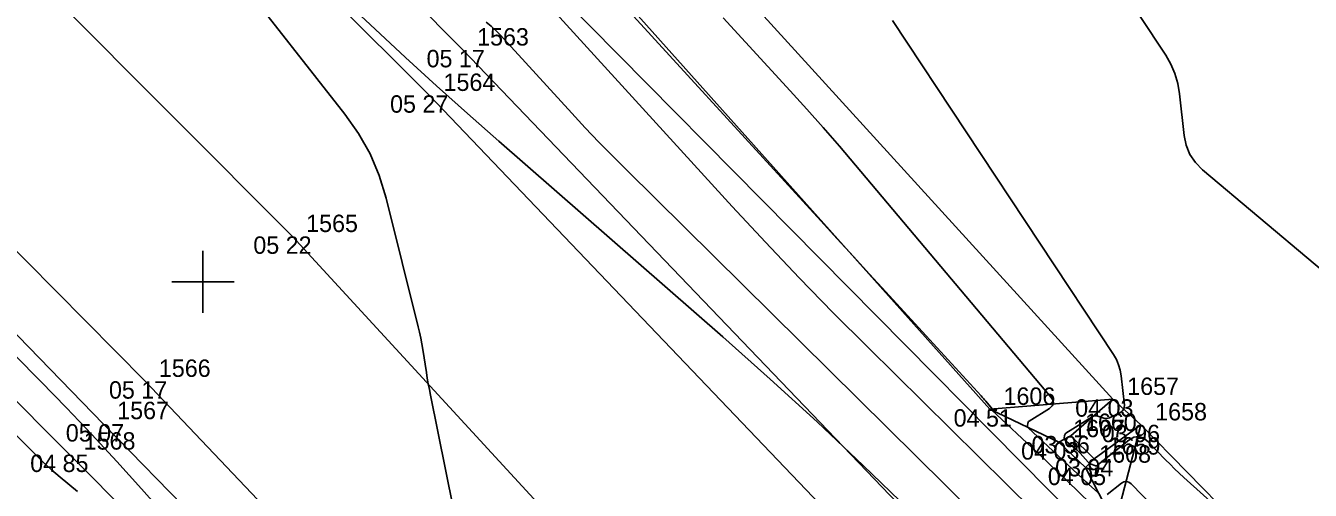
# Model space of a CAD drawing. Extents: x -711234 to -710007, y -1026313 to -1025448.
# Drawn here: x -710352.85 to -710332.18, y -1025703.35 to -1025695.88 of the extents above; entities that cross this region are included whole.
import ezdxf

# ---------------------------------------------------------------- set-up
doc = ezdxf.new("R2010")
doc.units = 0
for name, color, linetype in [('Ex_Major Contours', 7, 'Continuous'), ('Ex_Minor Contours', 7, 'Continuous'), ('Z_body', 7, 'Continuous'), ('Z_body_cisla', 7, 'Continuous'), ('Z_body_vysky_redukovane', 7, 'Continuous'), ('Z_hektometricka_sit', 7, 'Continuous'), ('Z_hrany_paty', 7, 'Continuous'), ('Z_katastr_hranice', 7, 'Continuous'), ('Z_komunikace', 7, 'Continuous'), ('Z_komunikace_osa', 7, 'Continuous'), ('Z_pole_rozhranni', 7, 'Continuous')]:
    doc.layers.add(name, color=color, linetype=linetype)

# ---------------------------------------------------------------- blocks, each defined once
blk = doc.blocks.new('POINT_DISPLAY')
blk.add_line((0, 0), (0, 0))

msp = doc.modelspace()

# ---------------------------------------------------------------- linework, layer by layer
at = {"layer": 'Ex_Major Contours'}
for points in [[(-710361.606, -1025693.861), (-710352.57, -1025702.9), (-710352.505, -1025702.963), (-710352.438, -1025703.025), (-710352.37, -1025703.086), (-710352.3, -1025703.145), (-710352.018, -1025703.376)], [(-710345.446, -1025695.826), (-710345.364, -1025695.889), (-710345.286, -1025695.959), (-710345.212, -1025696.034), (-710344.065, -1025697.289), (-710343.849, -1025697.522), (-710343.63, -1025697.753), (-710343.408, -1025697.981), (-710343.182, -1025698.206), (-710337.591, -1025703.725)], [(-710338.909, -1025695.795), (-710335.352, -1025701.172), (-710335.305, -1025701.252), (-710335.27, -1025701.335), (-710335.244, -1025701.422), (-710335.229, -1025701.512), (-710335.176, -1025701.985), (-710335.177, -1025702.022), (-710335.188, -1025702.054), (-710335.209, -1025702.081), (-710335.24, -1025702.102), (-710335.415, -1025702.188), (-710335.437, -1025702.196), (-710335.461, -1025702.2), (-710335.484, -1025702.199), (-710335.508, -1025702.193), (-710335.604, -1025702.16), (-710335.627, -1025702.154), (-710335.65, -1025702.154), (-710335.673, -1025702.159), (-710335.694, -1025702.17), (-710336.116, -1025702.437), (-710336.124, -1025702.443), (-710336.131, -1025702.451), (-710336.135, -1025702.46), (-710336.138, -1025702.471), (-710336.145, -1025702.515), (-710336.146, -1025702.526), (-710336.143, -1025702.535), (-710336.138, -1025702.544), (-710336.131, -1025702.551), (-710335.987, -1025702.664), (-710335.961, -1025702.686), (-710335.935, -1025702.709), (-710335.911, -1025702.733), (-710335.888, -1025702.758), (-710335.756, -1025702.904), (-710335.746, -1025702.915), (-710335.734, -1025702.923), (-710335.722, -1025702.93), (-710335.708, -1025702.936), (-710335.652, -1025702.955), (-710335.638, -1025702.958), (-710335.625, -1025702.958), (-710335.613, -1025702.954), (-710335.601, -1025702.946), (-710335.102, -1025702.549), (-710335.023, -1025702.502), (-710334.946, -1025702.489), (-710334.871, -1025702.512), (-710334.799, -1025702.568), (-710334.513, -1025702.862), (-710334.441, -1025702.935), (-710334.368, -1025703.007), (-710334.294, -1025703.078), (-710334.218, -1025703.147), (-710333.639, -1025703.671)], [(-710347.01, -1025707.804), (-710350.989, -1025703.329), (-710351.385, -1025702.89), (-710351.787, -1025702.457), (-710352.194, -1025702.029), (-710352.608, -1025701.606), (-710354.273, -1025699.928)]]:
    msp.add_lwpolyline(points, dxfattribs=at)
at = {"layer": 'Ex_Minor Contours'}
for points in [[(-710330.296, -1025701.243), (-710333.918, -1025698.198), (-710334.033, -1025698.082), (-710334.121, -1025697.951), (-710334.181, -1025697.805), (-710334.213, -1025697.645), (-710334.288, -1025696.974), (-710334.316, -1025696.81), (-710334.362, -1025696.652), (-710334.428, -1025696.501), (-710334.511, -1025696.357), (-710337.061, -1025692.503)], [(-710349.875, -1025693.472), (-710347.232, -1025695.939), (-710346.74, -1025696.394), (-710346.245, -1025696.846), (-710345.745, -1025697.293), (-710345.242, -1025697.736), (-710341.638, -1025700.886), (-710340.874, -1025701.564), (-710340.121, -1025702.253), (-710339.378, -1025702.953), (-710338.646, -1025703.665), (-710331.327, -1025710.89)], [(-710335.538, -1025703.742), (-710336.093, -1025703.207), (-710336.214, -1025703.091), (-710336.336, -1025702.976), (-710336.458, -1025702.861), (-710336.58, -1025702.747), (-710337.316, -1025702.062), (-710337.317, -1025702.06), (-710337.316, -1025702.057), (-710337.303, -1025702.049), (-710337.301, -1025702.048), (-710337.301, -1025702.046), (-710337.301, -1025702.045), (-710337.302, -1025702.043), (-710337.407, -1025701.918), (-710337.425, -1025701.897), (-710337.443, -1025701.876), (-710337.462, -1025701.855), (-710337.481, -1025701.834), (-710339.013, -1025700.164), (-710339.275, -1025699.879), (-710339.536, -1025699.593), (-710339.798, -1025699.307), (-710340.059, -1025699.022), (-710343.713, -1025695.023)], [(-710345.611, -1025705.436), (-710346.34, -1025701.824), (-710346.358, -1025701.733), (-710346.375, -1025701.641), (-710346.391, -1025701.549), (-710346.406, -1025701.457), (-710346.464, -1025701.088), (-710346.48, -1025700.996), (-710346.497, -1025700.905), (-710346.517, -1025700.813), (-710346.539, -1025700.723), (-710347.053, -1025698.657), (-710347.165, -1025698.291), (-710347.312, -1025697.943), (-710347.496, -1025697.613), (-710347.717, -1025697.301), (-710349.461, -1025695.078)], [(-710344.319, -1025695.686), (-710341.485, -1025698.787), (-710340.951, -1025699.364), (-710340.409, -1025699.934), (-710339.86, -1025700.497), (-710339.304, -1025701.054), (-710335.744, -1025704.567), (-710335.553, -1025704.755), (-710335.362, -1025704.942), (-710335.169, -1025705.129), (-710334.976, -1025705.315), (-710334.203, -1025706.059), (-710334.01, -1025706.246), (-710333.819, -1025706.434), (-710333.63, -1025706.624), (-710333.443, -1025706.815), (-710330.108, -1025710.25)], [(-710341.63, -1025695.753), (-710340.554, -1025696.927), (-710340.286, -1025697.222), (-710340.022, -1025697.519), (-710339.76, -1025697.82), (-710339.502, -1025698.123), (-710336.355, -1025701.86), (-710336.324, -1025701.91), (-710336.318, -1025701.956), (-710336.337, -1025701.998), (-710336.382, -1025702.036), (-710336.708, -1025702.242), (-710336.716, -1025702.248), (-710336.722, -1025702.256), (-710336.726, -1025702.264), (-710336.729, -1025702.274), (-710336.735, -1025702.316), (-710336.736, -1025702.326), (-710336.734, -1025702.335), (-710336.73, -1025702.344), (-710336.723, -1025702.352), (-710335.852, -1025703.162), (-710335.826, -1025703.187), (-710335.799, -1025703.211), (-710335.773, -1025703.235), (-710335.746, -1025703.259), (-710335.608, -1025703.384)], [(-710335.451, -1025703.423), (-710335.223, -1025703.242), (-710335.182, -1025703.218), (-710335.142, -1025703.211), (-710335.103, -1025703.223), (-710335.065, -1025703.252), (-710332.011, -1025706.4)]]:
    msp.add_lwpolyline(points, dxfattribs=at)
at = {"layer": 'Z_hektometricka_sit'}
for p, q in [((-710350, -1025699.5), (-710350, -1025700.5)), ((-710350.5, -1025700), (-710349.5, -1025700))]:
    msp.add_line(p, q, dxfattribs=at)
at = {"layer": 'Z_hrany_paty'}
for p, q in [((-710357.09, -1025684.89), (-710345.82, -1025696.27)), ((-710362.55, -1025691.04), (-710351.6, -1025702.29)), ((-710363.12, -1025691.77), (-710352.15, -1025702.78)), ((-710343.93, -1025694.68), (-710337.34, -1025702.05)), ((-710345.82, -1025696.27), (-710330.09, -1025712.66)), ((-710337.34, -1025702.05), (-710335.36, -1025701.89)), ((-710337.34, -1025702.05), (-710336.23, -1025702.58)), ((-710336.04, -1025702.48), (-710335.36, -1025701.89)), ((-710351.6, -1025702.29), (-710335.91, -1025718.34)), ((-710336.23, -1025702.58), (-710336.04, -1025702.48)), ((-710336.04, -1025702.48), (-710335.66, -1025702.85)), ((-710334.91, -1025702.3), (-710335.66, -1025702.85)), ((-710335.33, -1025703.9), (-710334.91, -1025702.3)), ((-710336.23, -1025702.58), (-710335.8, -1025702.99)), ((-710352.15, -1025702.78), (-710344.38, -1025710.56)), ((-710335.66, -1025702.85), (-710335.8, -1025702.99)), ((-710335.8, -1025702.99), (-710335.33, -1025703.9))]:
    msp.add_line(p, q, dxfattribs=at)
at = {"layer": 'Z_katastr_hranice'}
msp.add_lwpolyline([(-710600.21, -1025504.82), (-710580.45, -1025521.54), (-710492.86, -1025583.88), (-710429.93, -1025627.5), (-710391.58, -1025654.85), (-710379.57, -1025662.83), (-710367.07, -1025673.36), (-710347.9, -1025691.71), (-710333.8, -1025705.97), (-710271.15, -1025774.38), (-710237.36, -1025811.14)], dxfattribs=at)
at = {"layer": 'Z_komunikace'}
for p, q in [((-710357.8, -1025685.58), (-710346.36, -1025697)), ((-710362.04, -1025690.37), (-710350.93, -1025701.6)), ((-710346.36, -1025697), (-710330.65, -1025713.43)), ((-710350.93, -1025701.6), (-710335.44, -1025717.9))]:
    msp.add_line(p, q, dxfattribs=at)
at = {"layer": 'Z_komunikace_osa'}
for p, q in [((-710359.77, -1025688.03), (-710348.56, -1025699.27)), ((-710348.56, -1025699.27), (-710333.28, -1025715.87))]:
    msp.add_line(p, q, dxfattribs=at)
at = {"layer": 'Z_pole_rozhranni'}
for p, q in [((-710341.25, -1025695.42), (-710335.36, -1025701.89)), ((-710335.36, -1025701.89), (-710334.91, -1025702.3)), ((-710334.91, -1025702.3), (-710314.95, -1025722.66))]:
    msp.add_line(p, q, dxfattribs=at)

# ---------------------------------------------------------------- block references
at = {"layer": 'Z_body'}
for p in [(-710345.82, -1025696.27), (-710346.36, -1025697), (-710348.56, -1025699.27), (-710350.93, -1025701.6), (-710337.34, -1025702.05), (-710335.36, -1025701.89), (-710351.6, -1025702.29), (-710336.04, -1025702.48), (-710334.91, -1025702.3), (-710336.23, -1025702.58), (-710352.15, -1025702.78), (-710335.66, -1025702.85), (-710335.8, -1025702.99)]:
    msp.add_blockref('POINT_DISPLAY', p, dxfattribs=at)

# ---------------------------------------------------------------- texts
at = {"layer": 'Z_body_cisla'}
for s, p in [('1563', (-710345.59, -1025696.2)), ('1564', (-710346.13, -1025696.93)), ('1565', (-710348.34, -1025699.2)), ('1566', (-710350.71, -1025701.53)), ('1657', (-710335.13, -1025701.82)), ('1606', (-710337.12, -1025701.98)), ('1567', (-710351.38, -1025702.21)), ('1658', (-710334.68, -1025702.23)), ('1607', (-710336, -1025702.5)), ('1660', (-710335.81, -1025702.4)), ('1568', (-710351.92, -1025702.7)), ('1659', (-710335.43, -1025702.78)), ('1608', (-710335.58, -1025702.91))]:
    msp.add_text(s, height=0.28, dxfattribs=at).set_placement(p)
at = {"layer": 'Z_body_vysky_redukovane'}
for s, p in [('05 17', (-710346.403, -1025696.55)), ('05 27', (-710346.99, -1025697.28)), ('05 22', (-710349.19, -1025699.55)), ('05 17', (-710351.513, -1025701.88)), ('04 51', (-710337.923, -1025702.33)), ('04 03', (-710335.967, -1025702.17)), ('05 07', (-710352.207, -1025702.57)), ('03 96', (-710336.67, -1025702.76)), ('03 96', (-710335.54, -1025702.58)), ('04 03', (-710336.837, -1025702.86)), ('04 85', (-710352.78, -1025703.06)), ('03 94', (-710336.29, -1025703.13)), ('04 05', (-710336.407, -1025703.27))]:
    msp.add_text(s, height=0.28, dxfattribs=at).set_placement(p)

doc.saveas('drawing.dxf')
